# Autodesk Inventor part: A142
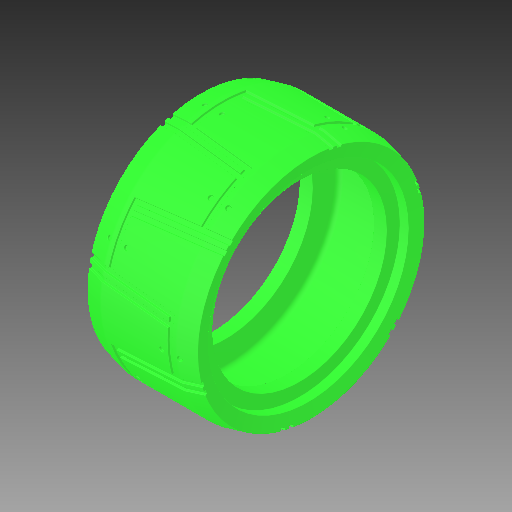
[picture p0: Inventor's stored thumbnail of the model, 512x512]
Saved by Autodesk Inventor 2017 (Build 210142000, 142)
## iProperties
Part Number: A142
Material: Générique
Document SubType Name: Modeling
Designer: ficho
Density: 1 g/cm^3
Appearance: Par défaut
Author: ficho
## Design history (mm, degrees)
feature "Solid1"
node "Solide1"
